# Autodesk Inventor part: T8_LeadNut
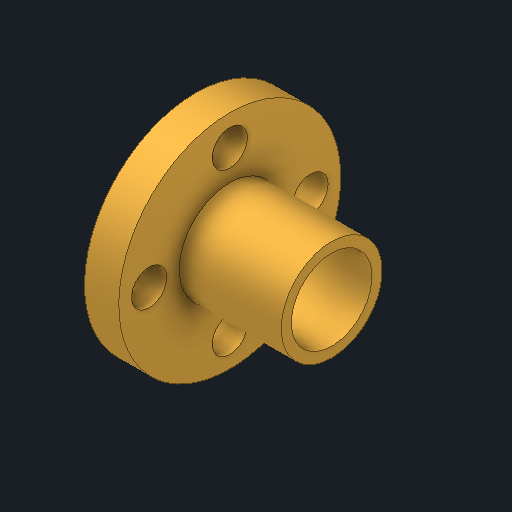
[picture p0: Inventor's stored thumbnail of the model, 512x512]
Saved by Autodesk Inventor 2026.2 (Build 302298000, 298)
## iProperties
Created: 2025-11
Part Number: T8_LeadNut
Material: 황동, 연질 노란색
Document SubType Name: Modeling
Designer: work
Density: 8.47 g/cm^3
Appearance: 황동 - 새틴
Author: work
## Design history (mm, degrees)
sketch "스케치1"
  geometry: L1 (0, 0)-(15, 0); L2 (15, 0)-(15, 5); L3 (15, 5)-(0, 5); L4 (0, 5)-(0, 0); L5 (1.5, 5)-(1.5, 11); L6 (1.5, 11)-(4.9, 11); L7 (4.9, 11)-(4.9, 5); L8 (0, 4)-(15, 4); 1 further point
  constraints: 16 end point, 6 perpendicular, 4 point on line, 1 horizontal, 1 midpoint, 1 vertical
  dimensions: "d0" = 8 diameter of L8 L1; "d1" = 10 diameter of L3 L1; "d2" = 22 diameter of point (3.2, 11) L1; "d3" = 3.4 distance of L5.end L6.end; "d4" = 1.5 distance from line of L3.end L5; "d5" = 15 distance of L2.end L3.end
revolve "회전1" sketch "스케치1" stored, may be unused: angle "d6" = 90 deg
sketch "스케치2"
  geometry: L1 (0, 0)-(-8, 0); C1 r 1.75 at (-8, 0); C2 r 5 at (0, 0) reference; C3 r 11 at (0, 0) reference; C4 r 1.75 at (0, -8); C5 r 1.75 at (8, 0); C6 r 1.75 at (0, 8); 1 further point
  constraints: 4 centre point, 2 end point, 1 horizontal, 9 other
  dimensions: "d7" = 3.5 diameter of C1; "d9" = 8 distance of point (0, 0) L1.end; "d12" = 360 deg dimension on C2.centre L1.end (derived)
extrude "돌출1" cut sketch "스케치2" distance "d14" = 10; taper "d15" = 0 deg
node "솔리드1"
node "투영된 루프1"
node "스케치 - 원형 패턴1" dims "d12" = 360 deg (derived)
